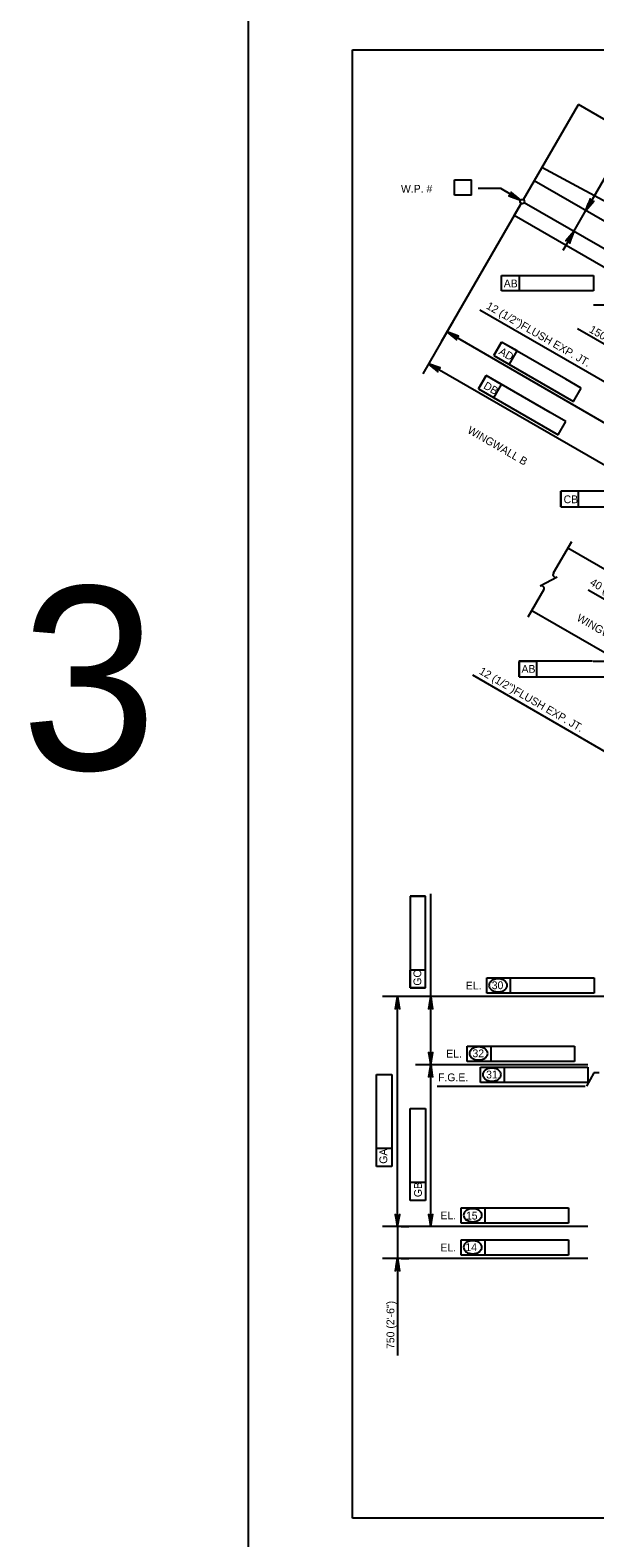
# Model space of a CAD drawing. Extents: x 638340 to 640241, y 295465 to 298435.
# Drawn here: x 638352 to 638568, y 296661 to 297240 of the extents above; entities that cross this region are included whole.
import ezdxf

# ---------------------------------------------------------------- set-up
doc = ezdxf.new("R2010")
doc.units = 0
for name, color, linetype in [('1', 7, 'Continuous'), ('10', 7, 'Continuous'), ('2', 7, 'Continuous'), ('3', 7, 'Continuous'), ('4', 7, 'Continuous'), ('53', 7, 'Continuous'), ('PLT-BNDY', 7, 'Continuous')]:
    doc.layers.add(name, color=color, linetype=linetype)

# ---------------------------------------------------------------- blocks, each defined once
blk = doc.blocks.new('V')
at = {"layer": '1'}
blk.add_line((0, 0), (0, 0), dxfattribs=at)

msp = doc.modelspace()

# ---------------------------------------------------------------- linework, layer by layer
at = {"layer": '10'}
for p, q in [((638541.04, 297174.86), (638562.15, 297211.42)), ((638636.98, 297168.22), (638562.15, 297211.42)), ((638615.83, 297150.61), (638548.15, 297187.17)), ((638611.82, 297143.67), (638545.23, 297182.12)), ((638537.54, 297168.8), (638540.19, 297173.39)), ((638607.21, 297135.68), (638541.35, 297173.7)), ((638615.8, 297123.61), (638537.54, 297168.8)), ((638613.57, 297008.95), (638558.08, 297040.99)), ((638599.73, 296984.98), (638544.23, 297017.02))]:
    msp.add_line(p, q, dxfattribs=at)
at = {"layer": '2'}
for p, q in [((638475.46, 296668.46), (638475.46, 297232.46)), ((638475.46, 297232.46), (639261.46, 297232.46)), ((639261.46, 296668.46), (638475.46, 296668.46))]:
    msp.add_line(p, q, dxfattribs=at)
at = {"layer": '3'}
for p, q in [((638566.54, 297173.23), (638579.21, 297195.19)), ((638514.59, 297182.52), (638521.18, 297182.52)), ((638514.59, 297176.61), (638514.59, 297182.52)), ((638521.18, 297176.61), (638521.18, 297182.52)), ((638532.4, 297179.15), (638523.7, 297179.15)), ((638539.93, 297174.63), (638532.4, 297179.15)), ((638539.84, 297172.79), (638509.49, 297120.23)), ((638521.18, 297176.61), (638514.59, 297176.61)), ((638560.45, 297162.68), (638565.06, 297170.67)), ((638558.97, 297160.12), (638556.21, 297155.34)), ((638532.69, 297145.76), (638539.54, 297145.76)), ((638532.69, 297139.85), (638532.69, 297145.76)), ((638539.54, 297139.85), (638539.54, 297145.76)), ((638539.54, 297145.76), (638568, 297145.76)), ((638568, 297145.76), (638568, 297139.85)), ((638568, 297139.85), (638532.69, 297139.85)), ((638585.07, 297097.33), (638524.29, 297132.45)), ((638607.92, 297134.38), (638568.02, 297134.38)), ((638514.06, 297128.14), (638502.43, 297107.99)), ((638511.71, 297124.06), (638578.3, 297085.61)), ((638532.67, 297120.17), (638529.72, 297115.06)), ((638529.72, 297115.06), (638532.67, 297120.17)), ((638557.32, 297105.94), (638532.67, 297120.17)), ((638538.6, 297116.75), (638532.67, 297120.17)), ((638583.57, 297112.7), (638561.85, 297125.23)), ((638529.72, 297115.06), (638560.29, 297097.41)), ((638535.65, 297111.63), (638538.6, 297116.75)), ((638573.49, 297072.08), (638504.64, 297111.82)), ((638526.73, 297107.29), (638523.78, 297102.17)), ((638523.78, 297102.17), (638526.73, 297107.29)), ((638551.38, 297093.06), (638526.73, 297107.29)), ((638532.66, 297103.86), (638526.73, 297107.29)), ((638529.71, 297098.75), (638532.66, 297103.86)), ((638563.25, 297102.52), (638557.32, 297105.94)), ((638560.29, 297097.41), (638563.25, 297102.52)), ((638523.78, 297102.17), (638554.35, 297084.52)), ((638557.3, 297089.63), (638551.38, 297093.06)), ((638554.35, 297084.52), (638557.3, 297089.63)), ((638555.41, 297062.86), (638555.41, 297056.96)), ((638583.87, 297062.86), (638555.41, 297062.86)), ((638562.25, 297062.86), (638555.41, 297062.86)), ((638555.41, 297056.96), (638555.41, 297062.86)), ((638562.25, 297056.96), (638562.25, 297062.86)), ((638555.41, 297056.96), (638590.71, 297056.96)), ((638604.13, 297002.86), (638565.91, 297024.93)), ((638567.63, 296997.62), (638539.33, 296997.62)), ((638539.38, 296997.56), (638539.38, 296991.66)), ((638539.38, 296991.66), (638539.38, 296997.56)), ((638546.23, 296997.56), (638539.4, 296997.56)), ((638546.23, 296991.66), (638546.23, 296997.56)), ((638574.68, 296997.56), (638567.86, 296997.56)), ((638578.22, 296959.54), (638521.61, 296992.22)), ((638539.38, 296991.66), (638574.68, 296991.66)), ((638497.57, 296907.44), (638497.57, 296872.13)), ((638503.48, 296907.44), (638497.57, 296907.44)), ((638497.57, 296907.44), (638503.48, 296907.44)), ((638503.48, 296878.98), (638503.48, 296907.44)), ((638503.48, 296900.59), (638503.48, 296907.44)), ((638505.45, 296842.64), (638505.45, 296908.27)), ((638497.57, 296872.13), (638497.57, 296878.98)), ((638503.48, 296878.98), (638497.57, 296878.98)), ((638503.48, 296872.13), (638503.48, 296878.98)), ((638497.57, 296872.13), (638503.48, 296872.13)), ((638503.48, 296872.13), (638497.57, 296872.13)), ((638526.96, 296875.97), (638536.13, 296875.97)), ((638526.96, 296870.07), (638526.96, 296875.97)), ((638536.13, 296870.07), (638536.13, 296875.97)), ((638536.13, 296875.97), (638568.17, 296875.97)), ((638568.17, 296875.97), (638568.17, 296870.07)), ((638619.07, 296868.79), (638486.89, 296868.79)), ((638493.75, 296868.79), (638488.23, 296868.79)), ((638498.99, 296868.79), (638488.23, 296868.79)), ((638492.66, 296780.51), (638492.66, 296868.79)), ((638507.91, 296868.79), (638501.02, 296868.79)), ((638568.17, 296870.07), (638526.96, 296870.07)), ((638519.46, 296849.83), (638528.63, 296849.83)), ((638519.46, 296843.92), (638519.46, 296849.83)), ((638528.63, 296843.92), (638528.63, 296849.83)), ((638528.63, 296849.83), (638560.67, 296849.83)), ((638560.67, 296849.83), (638560.67, 296843.92)), ((638565.81, 296842.64), (638499.67, 296842.64)), ((638510.8, 296842.64), (638501.02, 296842.64)), ((638505.45, 296780.51), (638505.45, 296842.64)), ((638560.67, 296843.92), (638519.46, 296843.92)), ((638484.61, 296838.91), (638490.51, 296838.91)), ((638484.61, 296810.45), (638484.61, 296838.91)), ((638490.51, 296838.91), (638490.51, 296803.61)), ((638524.58, 296841.69), (638533.76, 296841.69)), ((638524.58, 296835.78), (638524.58, 296841.69)), ((638533.76, 296835.78), (638533.76, 296841.69)), ((638533.76, 296841.69), (638565.79, 296841.69)), ((638568.04, 296839.56), (638565.27, 296834.37)), ((638565.79, 296841.69), (638565.79, 296835.78)), ((638507.93, 296834.37), (638564.74, 296834.37)), ((638565.79, 296835.78), (638524.58, 296835.78)), ((638497.53, 296825.84), (638503.44, 296825.84)), ((638497.53, 296797.38), (638497.53, 296825.84)), ((638503.44, 296825.84), (638503.44, 296790.54)), ((638484.61, 296803.61), (638484.61, 296810.45)), ((638490.51, 296810.45), (638484.61, 296810.45)), ((638490.51, 296803.61), (638484.61, 296803.61)), ((638497.53, 296790.54), (638497.53, 296797.38)), ((638503.44, 296797.38), (638497.53, 296797.38)), ((638503.44, 296790.54), (638497.53, 296790.54)), ((638517.21, 296787.7), (638526.38, 296787.7)), ((638517.21, 296781.79), (638517.21, 296787.7)), ((638526.38, 296781.79), (638526.38, 296787.7)), ((638526.38, 296787.7), (638558.42, 296787.7)), ((638558.42, 296787.7), (638558.42, 296781.79)), ((638565.81, 296780.51), (638486.89, 296780.51)), ((638493.75, 296780.51), (638488.23, 296780.51)), ((638494.22, 296780.51), (638488.23, 296780.51)), ((638498.99, 296780.51), (638488.23, 296780.51)), ((638492.66, 296780.51), (638492.66, 296768.21)), ((638494.14, 296780.51), (638497.09, 296780.51)), ((638558.42, 296781.79), (638517.21, 296781.79)), ((638517.21, 296769.49), (638517.21, 296775.39)), ((638517.21, 296775.39), (638526.38, 296775.39)), ((638526.38, 296769.49), (638526.38, 296775.39)), ((638526.38, 296775.39), (638558.42, 296775.39)), ((638558.42, 296775.39), (638558.42, 296769.49)), ((638565.81, 296768.21), (638486.89, 296768.21)), ((638492.66, 296768.21), (638492.66, 296730.95)), ((638494.14, 296768.21), (638497.09, 296768.21)), ((638558.42, 296769.49), (638517.21, 296769.49))]:
    msp.add_line(p, q, dxfattribs=at)
for points in [[(638539.93, 297174.63), (638536.38, 297177.78), (638536.56, 297177.38), (638536.56, 297177.02), (638536.45, 297176.72), (638536.24, 297176.48), (638535.92, 297176.31), (638535.48, 297176.28), (638539.93, 297174.63), (638535.92, 297176.31), (638536.24, 297176.48), (638539.93, 297174.63), (638536.45, 297176.72), (638536.56, 297177.02), (638539.93, 297174.63), (638536.56, 297177.38)], [(638565.06, 297170.67), (638568.14, 297174.27), (638567.75, 297174.08), (638567.39, 297174.08), (638567.09, 297174.19), (638566.84, 297174.39), (638566.67, 297174.71), (638566.63, 297175.14), (638565.06, 297170.67), (638566.67, 297174.71), (638566.84, 297174.39), (638565.06, 297170.67), (638567.09, 297174.19), (638567.39, 297174.08), (638565.06, 297170.67), (638567.75, 297174.08)], [(638560.45, 297162.68), (638557.36, 297159.08), (638557.75, 297159.27), (638558.12, 297159.27), (638558.41, 297159.16), (638558.66, 297158.96), (638558.84, 297158.64), (638558.87, 297158.2), (638560.45, 297162.68), (638558.84, 297158.64), (638558.66, 297158.96), (638560.45, 297162.68), (638558.41, 297159.16), (638558.12, 297159.27), (638560.45, 297162.68), (638557.75, 297159.27)], [(638511.71, 297124.06), (638515.31, 297120.97), (638515.12, 297121.37), (638515.12, 297121.73), (638515.23, 297122.03), (638515.43, 297122.27), (638515.75, 297122.45), (638516.18, 297122.49), (638511.71, 297124.06), (638515.75, 297122.45), (638515.43, 297122.27), (638511.71, 297124.06), (638515.23, 297122.03), (638515.12, 297121.73), (638511.71, 297124.06), (638515.12, 297121.37)], [(638504.64, 297111.82), (638508.24, 297108.74), (638508.06, 297109.13), (638508.05, 297109.49), (638508.16, 297109.79), (638508.36, 297110.04), (638508.68, 297110.21), (638509.12, 297110.25), (638504.64, 297111.82), (638508.68, 297110.21), (638508.36, 297110.04), (638504.64, 297111.82), (638508.16, 297109.79), (638508.05, 297109.49), (638504.64, 297111.82), (638508.06, 297109.13)], [(638492.66, 296868.79), (638491.79, 296864.13), (638492.04, 296864.48), (638492.35, 296864.67), (638492.66, 296864.72), (638492.97, 296864.67), (638493.29, 296864.48), (638493.54, 296864.13), (638492.66, 296868.79), (638493.29, 296864.48), (638492.97, 296864.67), (638492.66, 296868.79), (638492.66, 296864.72), (638492.35, 296864.67), (638492.66, 296868.79), (638492.04, 296864.48)], [(638505.45, 296868.79), (638504.58, 296864.13), (638504.82, 296864.48), (638505.14, 296864.67), (638505.45, 296864.72), (638505.76, 296864.67), (638506.07, 296864.48), (638506.32, 296864.13), (638505.45, 296868.79), (638506.07, 296864.48), (638505.76, 296864.67), (638505.45, 296868.79), (638505.45, 296864.72), (638505.14, 296864.67), (638505.45, 296868.79), (638504.82, 296864.48)], [(638505.45, 296842.64), (638506.32, 296847.3), (638506.07, 296846.94), (638505.76, 296846.76), (638505.45, 296846.7), (638505.14, 296846.76), (638504.82, 296846.94), (638504.58, 296847.3), (638505.45, 296842.64), (638504.82, 296846.94), (638505.14, 296846.76), (638505.45, 296842.64), (638505.45, 296846.7), (638505.76, 296846.76), (638505.45, 296842.64), (638506.07, 296846.94)], [(638505.45, 296842.64), (638504.58, 296837.98), (638504.82, 296838.34), (638505.14, 296838.52), (638505.45, 296838.58), (638505.76, 296838.52), (638506.07, 296838.34), (638506.32, 296837.98), (638505.45, 296842.64), (638506.07, 296838.34), (638505.76, 296838.52), (638505.45, 296842.64), (638505.45, 296838.58), (638505.14, 296838.52), (638505.45, 296842.64), (638504.82, 296838.34)], [(638492.66, 296780.51), (638493.54, 296785.17), (638493.29, 296784.81), (638492.97, 296784.62), (638492.66, 296784.57), (638492.35, 296784.62), (638492.04, 296784.81), (638491.79, 296785.17), (638492.66, 296780.51), (638492.04, 296784.81), (638492.35, 296784.62), (638492.66, 296780.51), (638492.66, 296784.57), (638492.97, 296784.62), (638492.66, 296780.51), (638493.29, 296784.81)], [(638505.45, 296780.51), (638506.32, 296785.17), (638506.07, 296784.81), (638505.76, 296784.62), (638505.45, 296784.57), (638505.14, 296784.62), (638504.82, 296784.81), (638504.58, 296785.17), (638505.45, 296780.51), (638504.82, 296784.81), (638505.14, 296784.62), (638505.45, 296780.51), (638505.45, 296784.57), (638505.76, 296784.62), (638505.45, 296780.51), (638506.07, 296784.81)], [(638492.66, 296768.21), (638491.79, 296763.54), (638492.04, 296763.9), (638492.35, 296764.09), (638492.66, 296764.14), (638492.97, 296764.09), (638493.29, 296763.9), (638493.54, 296763.54), (638492.66, 296768.21), (638493.29, 296763.9), (638492.97, 296764.09), (638492.66, 296768.21), (638492.66, 296764.14), (638492.35, 296764.09), (638492.66, 296768.21), (638492.04, 296763.9)]]:
    msp.add_lwpolyline(points, dxfattribs=at)
for points in [[(638537.14, 297175.73), (638537.65, 297176.57), (638539.93, 297174.63)], [(638566.11, 297173.47), (638566.96, 297172.98), (638565.06, 297170.67)], [(638558.54, 297160.37), (638559.39, 297159.87), (638560.45, 297162.68)], [(638514.51, 297123.01), (638514.02, 297122.16), (638511.71, 297124.06)], [(638507.45, 297110.77), (638506.95, 297109.92), (638504.64, 297111.82)], [(638493.15, 296865.83), (638492.17, 296865.83), (638492.66, 296868.79)], [(638505.94, 296865.83), (638504.96, 296865.83), (638505.45, 296868.79)], [(638505.94, 296845.59), (638504.96, 296845.59), (638505.45, 296842.64)], [(638505.94, 296839.69), (638504.96, 296839.69), (638505.45, 296842.64)], [(638493.15, 296783.46), (638492.17, 296783.46), (638492.66, 296780.51)], [(638505.94, 296783.46), (638504.96, 296783.46), (638505.45, 296780.51)], [(638493.15, 296765.25), (638492.17, 296765.25), (638492.66, 296768.21)]]:
    msp.add_lwpolyline(points, close=True, dxfattribs=at)
msp.add_circle((638540.61, 297174.13), 0.85, dxfattribs=at)
for centre, radius, start, end in [((638529.66, 296873.13), 1.83, 149.97668, 180), ((638529.66, 296873.13), 1.83, 180, 210.02332), ((638530.47, 296872.66), 2.76, 125.63164, 149.97668), ((638530.47, 296873.59), 2.76, 210.02332, 234.36836), ((638530.99, 296871.93), 3.66, 106.53583, 125.63164), ((638530.99, 296874.33), 3.66, 234.36836, 253.46417), ((638531.34, 296870.77), 4.87, 90, 106.53583), ((638531.34, 296875.49), 4.87, 253.46417, 270), ((638531.34, 296870.77), 4.87, 73.46417, 90), ((638531.34, 296875.49), 4.87, 270, 286.53583), ((638531.68, 296871.93), 3.66, 54.36836, 73.46417), ((638531.68, 296874.33), 3.66, 286.53583, 305.63164), ((638532.21, 296872.66), 2.76, 30.02332, 54.36836), ((638532.21, 296873.59), 2.76, 305.63164, 329.97668), ((638533.02, 296873.13), 1.83, 0, 30.02332), ((638533.02, 296873.13), 1.83, 329.97668, 0), ((638522.16, 296846.98), 1.83, 149.97668, 180), ((638522.97, 296846.52), 2.76, 125.63164, 149.97668), ((638523.5, 296845.78), 3.66, 106.53583, 125.63164), ((638523.84, 296844.62), 4.87, 90, 106.53583), ((638523.84, 296844.62), 4.87, 73.46417, 90), ((638524.19, 296845.78), 3.66, 54.36836, 73.46417), ((638524.71, 296846.52), 2.76, 30.02332, 54.36836), ((638525.52, 296846.98), 1.83, 0, 30.02332), ((638522.16, 296846.98), 1.83, 180, 210.02332), ((638522.97, 296847.45), 2.76, 210.02332, 234.36836), ((638523.5, 296848.18), 3.66, 234.36836, 253.46417), ((638523.84, 296849.34), 4.87, 253.46417, 270), ((638523.84, 296849.34), 4.87, 270, 286.53583), ((638524.19, 296848.18), 3.66, 286.53583, 305.63164), ((638524.71, 296847.45), 2.76, 305.63164, 329.97668), ((638525.52, 296846.98), 1.83, 329.97668, 0), ((638527.28, 296838.84), 1.83, 149.97668, 180), ((638527.28, 296838.84), 1.83, 180, 210.02332), ((638528.09, 296838.37), 2.76, 125.63164, 149.97668), ((638528.09, 296839.31), 2.76, 210.02332, 234.36836), ((638528.62, 296837.64), 3.66, 106.53583, 125.63164), ((638528.62, 296840.04), 3.66, 234.36836, 253.46417), ((638528.96, 296836.48), 4.87, 90, 106.53583), ((638528.96, 296841.2), 4.87, 253.46417, 270), ((638528.96, 296836.48), 4.87, 73.46417, 90), ((638528.96, 296841.2), 4.87, 270, 286.53583), ((638529.31, 296837.64), 3.66, 54.36836, 73.46417), ((638529.31, 296840.04), 3.66, 286.53583, 305.63164), ((638529.83, 296838.37), 2.76, 30.02332, 54.36836), ((638529.83, 296839.31), 2.76, 305.63164, 329.97668), ((638530.64, 296838.84), 1.83, 0, 30.02332), ((638530.64, 296838.84), 1.83, 329.97668, 0), ((638519.91, 296784.85), 1.83, 149.97668, 180), ((638519.91, 296784.85), 1.83, 180, 210.02332), ((638520.71, 296784.38), 2.76, 125.63164, 149.97668), ((638520.71, 296785.31), 2.76, 210.02332, 234.36836), ((638521.24, 296783.65), 3.66, 106.53583, 125.63164), ((638521.58, 296782.49), 4.87, 90, 106.53583), ((638521.58, 296782.49), 4.87, 73.46417, 90), ((638521.93, 296783.65), 3.66, 54.36836, 73.46417), ((638522.45, 296784.38), 2.76, 30.02332, 54.36836), ((638522.45, 296785.31), 2.76, 305.63164, 329.97668), ((638523.26, 296784.85), 1.83, 0, 30.02332), ((638523.26, 296784.85), 1.83, 329.97668, 0), ((638521.24, 296786.05), 3.66, 234.36836, 253.46417), ((638521.58, 296787.21), 4.87, 253.46417, 270), ((638521.58, 296787.21), 4.87, 270, 286.53583), ((638521.93, 296786.05), 3.66, 286.53583, 305.63164), ((638519.91, 296772.55), 1.83, 149.97668, 180), ((638519.91, 296772.55), 1.83, 180, 210.02332), ((638520.71, 296772.08), 2.76, 125.63164, 149.97668), ((638521.24, 296771.35), 3.66, 106.53583, 125.63164), ((638521.58, 296770.19), 4.87, 90, 106.53583), ((638521.58, 296770.19), 4.87, 73.46417, 90), ((638521.93, 296771.35), 3.66, 54.36836, 73.46417), ((638522.45, 296772.08), 2.76, 30.02332, 54.36836), ((638523.26, 296772.55), 1.83, 0, 30.02332), ((638523.26, 296772.55), 1.83, 329.97668, 0), ((638520.71, 296773.01), 2.76, 210.02332, 234.36836), ((638521.24, 296773.75), 3.66, 234.36836, 253.46417), ((638521.58, 296774.91), 4.87, 253.46417, 270), ((638521.58, 296774.91), 4.87, 270, 286.53583), ((638521.93, 296773.75), 3.66, 286.53583, 305.63164), ((638522.45, 296773.01), 2.76, 305.63164, 329.97668)]:
    msp.add_arc(centre, radius, start, end, dxfattribs=at)
at = {"layer": '4'}
for p, q in [((638559.5, 297043.46), (638552.54, 297031.41)), ((638554, 297029.95), (638547.43, 297026.49)), ((638548.9, 297025.1), (638542.77, 297014.49)), ((638570.1, 296839.56), (638568.04, 296839.56))]:
    msp.add_line(p, q, dxfattribs=at)
for centre, start, end in [((638553.47, 297030.88), 150, 300), ((638547.93, 297025.55), 335.32859, 117.86724)]:
    msp.add_arc(centre, 1.07, start, end, dxfattribs=at)
at = {"layer": 'PLT-BNDY'}
msp.add_lwpolyline([(638435.46, 297247.46), (639276.46, 297247.46), (639276.46, 296653.46), (638435.46, 296653.46)], close=True, dxfattribs=at)

# ---------------------------------------------------------------- block references
at = {"layer": '3', "xscale": 0.78743606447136, "yscale": -0.78743606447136, "rotation": 180}
msp.add_blockref('V', (638554.62, 296997.62), dxfattribs=at)
at = {"layer": '3', "xscale": 0.78743606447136, "yscale": 0.78743606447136}
msp.add_blockref('V', (638542.89, 296775.25), dxfattribs=at)

# ---------------------------------------------------------------- texts
at = {"layer": '3'}
for s, p in [('W.P. #', (638494.04, 297177.54)), ('AB', (638533.51, 297141.18)), ('CB', (638556.49, 297058.28)), ('AB', (638540.33, 296993.15)), ('EL.', (638518.94, 296871.55)), ('30', (638528.88, 296871.66)), ('EL.', (638511.44, 296845.41)), ('32', (638521.49, 296845.52)), ('F.G.E.', (638508.26, 296836.31)), ('31', (638526.74, 296837.38)), ('EL.', (638509.19, 296783.27)), ('15', (638518.99, 296783.2)), ('EL.', (638509.19, 296770.97)), ('14', (638518.78, 296771.08))]:
    msp.add_text(s, height=3, dxfattribs=at).set_placement(p)
for s, height, rotation, p in [('12 (1/2")FLUSH EXP. JT.', 3.0001, 330, (638526.5, 297133.22)), ('150 (6")', 3, 330, (638566.02, 297124.14)), ('AD', 3, 330, (638531.33, 297115.69)), ('DB', 3, 330, (638525.45, 297102.55)), ('WINGWALL B', 3, 330, (638519.29, 297085.46)), (' 40 (1 1/2")CLR.', 3.0001, 330, (638565.35, 297027.59)), ('WINGWALL B', 3, 330, (638561.25, 297013.39)), ('12 (1/2")FLUSH EXP. JT.', 3.0001, 330, (638523.79, 296992.95)), ('GC', 3, 90, (638501.83, 296873.02)), ('GA', 3, 90, (638488.76, 296804.61)), ('GB', 3, 90, (638502.06, 296791.8)), ('750 (2\'-6")', 3.0001, 90, (638491.49, 296733.49))]:
    msp.add_text(s, height=height, rotation=rotation, dxfattribs=at).set_placement(p)
at = {"layer": '53'}
msp.add_text('3', height=70.32, dxfattribs=at).set_placement((638348.05, 296955.92))

doc.saveas('drawing.dxf')
